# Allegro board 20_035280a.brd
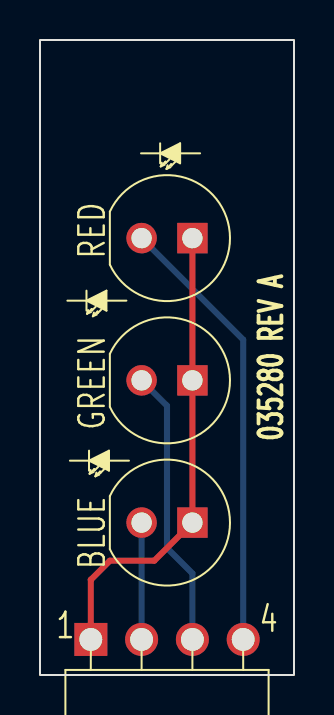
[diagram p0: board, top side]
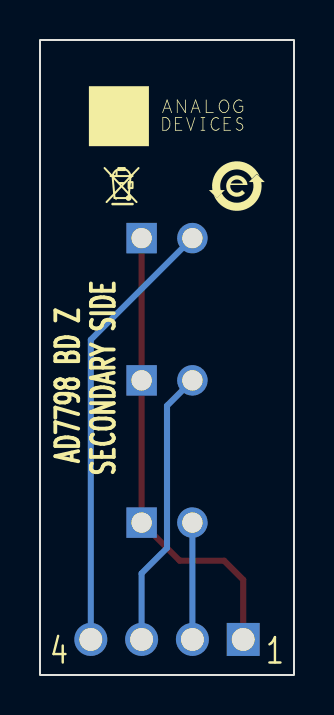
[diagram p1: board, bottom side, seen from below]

Outline 12.7 x 31.75 mm; copper layers: TOP, BOTTOM. Coordinates in mm from the lower left corner of the outline.
Outline path: rectangle 0,0 12.7,31.75

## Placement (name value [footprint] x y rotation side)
D1  C503B-RCS-CW0Z0AA1  [LEDRAD100D228H508]  7.62 21.84 180 top
D2  C503B-GCN-CY0C0791  [LEDRAD100D228H406]  7.62 14.73 180 top
D3  C503B-BCN-CV0Z0461  [LEDRAD100D228H406]  7.62 7.62 180 top
J1  TSW-104-09-G-S-RA  [CNSAMTECTSW-104-09-G-S-RA]  6.35 -1.33 0 top
NOREF  -  []  7.11 49.57 0 top
NOREF#2  -  []  12.7 -8.26 90 top
NOREF#3  -  []  2.54 1.78 0 top
NOREF#4  -  []  20.95 31.75 180 top
NOREF#5  -  []  12.7 0 90 top
NOREF#6  -  []  242.57 -180.66 0 top
NOREF#7  -  []  8.25 27.94 0 top
NOREF#8  -  []  334.65 -227.65 0 top
NOREF#9  -  []  100.08 -33.78 0 top
NOREF#10  -  []  0 40.01 270 top
NOREF#11  -  []  -164.64 -251.21 0 top
NOREF#12  -  []  0 0 0 top
NOREF#13  -  []  -93.48 -207.74 0 top
NOREF#14  -  []  157.13 -37.34 0 top
NOREF#15  -  []  0 31.75 0 top
NOREF#16  -  []  0 0 0 top
NOREF#17  -  []  2.54 1.78 0 top
NOREF#18  -  []  0 0 0 top
NOREF#19  -  []  182.88 52.07 0 top
NOREF#20  -  []  2.86 24.45 180 bottom
NOREF#21  -  []  8.57 24.45 180 bottom

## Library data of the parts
D1 = DIOLED: Tolerance: N/A; User Part Number: UPN; part number: DIOLED_TH-C503B-RCS-CW0Z0AA1,2.1V,N/A,E017527,LEDRAD100D228H508; tolerance: N/A
D2 = DIOLED: Tolerance: N/A; User Part Number: UPN; part number: DIOLED_TH-C503B-GCN-CY0C0791,3.2V,N/A,E017538,LEDRAD100D228H406; tolerance: N/A
D3 = DIOLED: Tolerance: N/A; User Part Number: UPN; part number: DIOLED_TH-C503B-BCN-CV0Z0461,3.2V,N/A,E017539,LEDRAD100D228H406; tolerance: N/A
J1 = CN4P: User Part Number: UPN; part number: CN4P_TH-TSW-104-09-G-S-RA,E007556,CNSAMTECTSW-104-09-G-S-RA

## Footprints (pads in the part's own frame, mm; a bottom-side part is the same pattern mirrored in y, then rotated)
CNSAMTECTSW-104-09-G-S-RA
  rect 1.651x1.651 hole 1.143: 1(-3.81,3.111)
  round 1.651 hole 1.143: 2(-1.27,3.111) 3(1.27,3.111) 4(3.81,3.111)
LEDRAD100D228H406
  rect 1.524x1.524 hole 1.016: A(0,0)
  round 1.524 hole 1.016: C(2.54,0)
LEDRAD100D228H508
  rect 1.524x1.524 hole 1.016: A(0,0)
  round 1.524 hole 1.016: C(2.54,0)

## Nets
UNNAMED_2_CN4P_I5_N1: D1.A(P) D2.A(P) D3.A(P) J1.1(N1)
UNNAMED_2_CN4P_I5_N2: D3.C(N) J1.2(N2)
UNNAMED_2_CN4P_I5_N3: D2.C(N) J1.3(N3)
UNNAMED_2_CN4P_I5_N4: D1.C(N) J1.4(N4)

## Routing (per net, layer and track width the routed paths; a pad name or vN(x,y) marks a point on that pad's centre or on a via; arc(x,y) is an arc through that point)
UNNAMED_2_CN4P_I5_N1: length 23.5
  TOP w0.305: D1.A D2.A D3.A 5.71,5.71 3.49,5.71 2.54,4.76 J1.1
UNNAMED_2_CN4P_I5_N2: length 5.8
  BOTTOM w0.305: J1.2 D3.C
UNNAMED_2_CN4P_I5_N3: length 14
  BOTTOM w0.305: D2.C 6.35,13.46 6.35,6.35 7.62,5.08 J1.3
UNNAMED_2_CN4P_I5_N4: length 22.2
  BOTTOM w0.305: D1.C 10.16,16.76 J1.4

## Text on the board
Ref Des/Silkscreen Bottom: SECONDARY SIDE | AD7798 BD Z
User.Comments: 11/06/12 | L.O. | WILL FACE DOWN INTO CONNECTOR. | INSTALL J1 ON TOP SIDE OF PCB SHORTER PINS | 01-035280
Ref Des/Silkscreen Top: 035280 REV A | RED | GREEN | BLUE
DIMENSION: PLATING OPTIONS: | -7. IMMERSION GOLD BOARD PLATING, 2-8 MICRO INCHES GOLD OVER 100 MICROINCHES | FABRICATION: | NOTES: | LOW STRESS NICKEL PLATING MIN PER QQ-N-290, CLASS I. | 16.   BOARDS TO BE SUPPLIED PANEL FORM BEST FIT. | SOLDER MASK;   SHALL BE LIQUID PHOTOIMAGABLE (LPI) APPLIED ON BOTH SIDES OVER BARE COPPER | SILK SCREEN;   SHALL BE PERMANENT NON-CONDUCTIVE EPOXY INK, COLOR WHITE. | U.L. RATING;   94VO MINIMUM. | 1.    REFER TO IPC-6010 SERIES (LATEST REV.), CLASS 2 FOR FABRICATION UNLESS | OTHERWISE SPECIFIED. | 2.    UNDIMENSIONED HOLES TO BE LOCATED WITHIN +/-.005 OF THEIR TRUE POSITION | WITH RESPECT TO ARTWORK. | 3.    PLATED HOLE WALL THICKNESS SHALL NOT BE LESS THAN .001 INCH MINIMUM | AVERAGE, WITH NO READING LESS THAN .0008 BY CROSS SECTION. | 4.    HOLE DIAMETERS APPLY AFTER PLATING. | 5.    FINISHED CONDUCTOR WIDTHS SHALL NOT BE REDUCED FROM THE NOMINAL, | INDICATED ON THE MASTER PATTERN, BY MORE THAN THE CONDUCTOR THICKNESS. | 6.    MINIMUM DESIGN LINE WIDTH IS .012 INCH. | 7.    MINIMUM DESIGN SPACING IS .012 INCH. | 8.    BOARD/PANEL MUST MEET IPC-A-600 (LATEST REV.) CLASS 2 FOR FLATNESS. | 9.    MFGR. TO LEGIBLY ETCH OR STAMP/SCREEN WITH PERMANENT NON-CONDUCTIVE INK | ON SECONDARY SIDE IN A CLEAR AREA UNLESS OTHERWISE INDICATED; | A. U.L. CODE             D. MFGR. LOGO - DESIGNATED AREA, | B. DATE CODE (STAMP)     E. SUCCESSFUL ELECTRICAL BOARD TEST. | C. FLAMMABILITY RATING   F. LOT NUMBER - DESIGNATED AREA. | 10.    NON-FUNCTIONAL PADS MAY BE REMOVED FROM INNER SIGNAL LAYERS AT MFGR. | DISCRETION. | 11.    IF PAD SIZES PROVIDED ARE NOT LARGE ENOUGH TO MAINTAIN ANNULAR RING | REQUIREMENT, MFGR. MAY TEAR DROP PADS TO MAINTAIN ANNULAR RING AT PAD | TO CIRCUIT INTERFACE ONLY AND MUST INSURE ELECTRICAL INTEGRITY. | 12.    REPAIRS PER IPC-R-700 ARE ALLOWED. | 13.    MODIFICATIONS TO THE ARTWORK, OTHER THAN THOSE DESCRIBED ON THE | FABRICATION DRAWING, ARE NOT ALLOWED WITHOUT WRITTEN AUTHORIZATION. | ACCEPTABILITY; PER ANALOG DEVICES, INC. SPECIFICATION TST00115 LATEST | REVISION. | MATERIALS;     IS410/370HR IN ACCORDANCE WITH IPC-L-130 (LATEST REV.). GLASS FABRIC | BASE, EPOXY RESIN, FIRE RESISTANT. | BONDING AGENT; PREIMPREGNATED B STAGE EPOXY GLASS CLOTH IN ACCORDANCE WITH | IPC-L-109 (LATEST REV.). | CLADDING;      EXTERNAL LAYERS 1/2 OZ. COPPER, OVERPLATE TO 1 1/2 OZ. | OR GOLD AND SHALL MEET IPC-SM-840 (LATEST REV) CLASS 3, COLOR GREEN. | 15.   IPC NETLIST TESTING TO BE DONE WITH NETLIST PROVIDED PRIOR TO FABRICATION. | ANY INTENTIONAL SHORTS WILL BE DEFINED IN SHORTS.TXT FILE.
User.9: 08-      -13 | PASTEMASK TOP
User.20: PRIMARY SIDE
User.25: PASTEMASK BOT | 08-      -14
User.39: FIGURE | SIZE | 40.0 | 45.0 | PLATED | FINISHED HOLES IN MILS | ALL UNITS ARE IN MILS | QTY | 6 | 4 | TOLERANCE/NOTES
